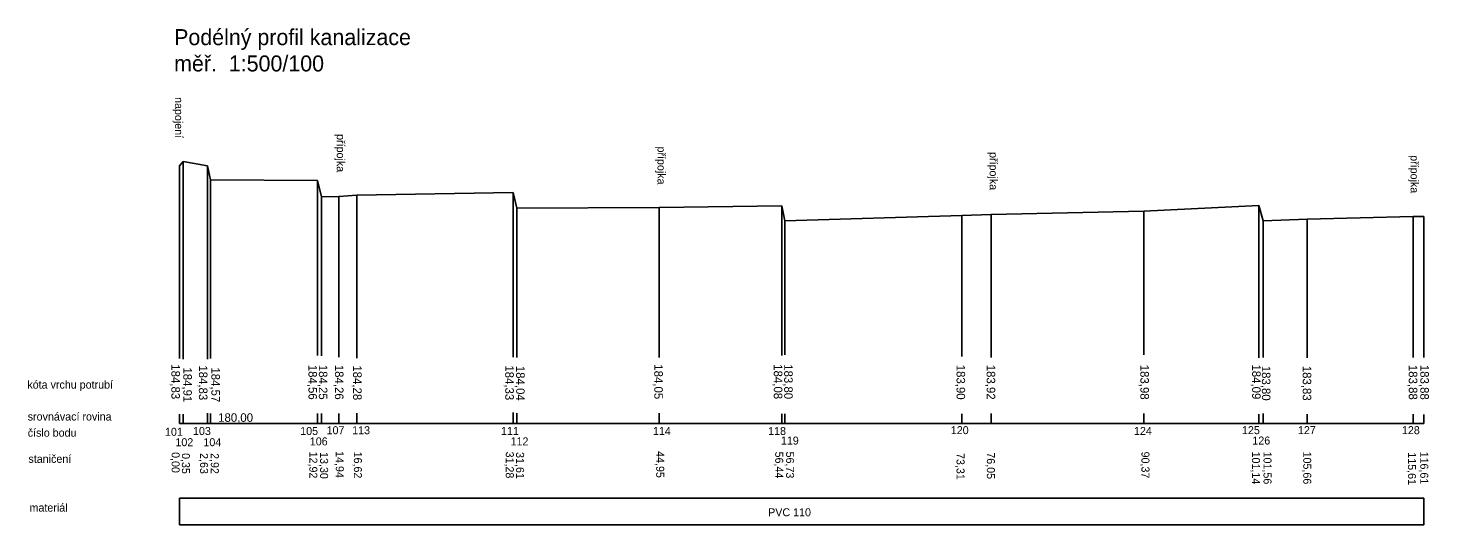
# Model space of a CAD drawing. Extents: x -598400 to -598043, y -1172615 to -1172551.
# Drawn here: x -598174.5 to -598043.2, y -1172597.3 to -1172550.7 of the extents above; entities that cross this region are included whole.
import ezdxf

# ---------------------------------------------------------------- set-up
doc = ezdxf.new("R2010")
doc.units = 0
doc.layers.add('2', color=7, linetype='Continuous')

msp = doc.modelspace()

# ---------------------------------------------------------------- linework, layer by layer
at = {"layer": '2'}
for p, q in [((-598159.922, -1172563.234), (-598160.272, -1172563.634)), ((-598160.272, -1172581.688), (-598160.272, -1172563.634)), ((-598157.642, -1172563.634), (-598159.922, -1172563.234)), ((-598159.922, -1172581.737), (-598159.922, -1172563.234)), ((-598157.352, -1172564.934), (-598157.642, -1172563.634)), ((-598157.642, -1172581.737), (-598157.642, -1172563.634)), ((-598147.352, -1172564.984), (-598157.352, -1172564.934)), ((-598157.352, -1172581.688), (-598157.352, -1172564.934)), ((-598146.972, -1172566.534), (-598147.352, -1172564.984)), ((-598147.352, -1172581.397), (-598147.352, -1172564.984)), ((-598145.332, -1172566.484), (-598146.972, -1172566.534)), ((-598143.652, -1172566.384), (-598145.332, -1172566.484)), ((-598145.332, -1172581.543), (-598145.332, -1172566.484)), ((-598128.992, -1172566.134), (-598143.652, -1172566.384)), ((-598143.652, -1172581.64), (-598143.652, -1172566.384)), ((-598128.662, -1172567.584), (-598128.992, -1172566.134)), ((-598128.992, -1172581.543), (-598128.992, -1172566.134)), ((-598146.972, -1172581.445), (-598146.972, -1172566.534)), ((-598115.322, -1172567.534), (-598128.662, -1172567.584)), ((-598128.662, -1172581.591), (-598128.662, -1172567.584)), ((-598103.832, -1172567.384), (-598115.322, -1172567.534)), ((-598115.322, -1172581.591), (-598115.322, -1172567.534)), ((-598103.542, -1172568.784), (-598103.832, -1172567.384)), ((-598103.832, -1172581.39), (-598103.832, -1172567.384)), ((-598059.132, -1172567.334), (-598069.902, -1172567.884)), ((-598058.712, -1172568.784), (-598059.132, -1172567.334)), ((-598059.132, -1172581.614), (-598059.132, -1172567.334)), ((-598086.962, -1172568.284), (-598103.542, -1172568.784)), ((-598103.542, -1172581.341), (-598103.542, -1172568.784)), ((-598084.222, -1172568.184), (-598086.962, -1172568.284)), ((-598086.962, -1172581.487), (-598086.962, -1172568.284)), ((-598069.902, -1172567.884), (-598084.222, -1172568.184)), ((-598084.222, -1172581.584), (-598084.222, -1172568.184)), ((-598069.902, -1172581.341), (-598069.902, -1172567.884)), ((-598054.612, -1172568.634), (-598058.712, -1172568.784)), ((-598058.712, -1172568.784), (-598058.712, -1172572.884)), ((-598058.712, -1172581.572), (-598058.712, -1172568.784)), ((-598044.662, -1172568.384), (-598054.612, -1172568.634)), ((-598054.612, -1172581.614), (-598054.612, -1172568.634)), ((-598043.662, -1172568.384), (-598044.662, -1172568.384)), ((-598044.662, -1172581.572), (-598044.662, -1172568.384)), ((-598043.662, -1172581.572), (-598043.662, -1172568.384)), ((-598160.272, -1172587.784), (-598160.272, -1172586.887)), ((-598159.922, -1172587.784), (-598159.922, -1172586.887)), ((-598157.642, -1172587.784), (-598157.642, -1172586.789)), ((-598157.352, -1172587.784), (-598157.352, -1172586.838)), ((-598147.352, -1172587.784), (-598147.352, -1172586.838)), ((-598146.972, -1172587.784), (-598146.972, -1172586.838)), ((-598145.332, -1172587.784), (-598145.332, -1172586.838)), ((-598143.652, -1172587.784), (-598143.652, -1172586.789)), ((-598128.992, -1172587.784), (-598128.992, -1172586.741)), ((-598128.662, -1172587.784), (-598128.662, -1172586.789)), ((-598115.322, -1172587.784), (-598115.322, -1172586.789)), ((-598103.832, -1172587.784), (-598103.832, -1172586.882)), ((-598103.542, -1172587.784), (-598103.542, -1172586.882)), ((-598086.962, -1172587.784), (-598086.962, -1172586.882)), ((-598084.222, -1172587.784), (-598084.222, -1172586.833)), ((-598069.902, -1172587.784), (-598069.902, -1172586.833)), ((-598059.132, -1172587.784), (-598059.132, -1172586.887)), ((-598058.712, -1172587.784), (-598058.712, -1172586.845)), ((-598054.612, -1172587.784), (-598054.612, -1172586.887)), ((-598044.662, -1172587.784), (-598044.662, -1172586.887)), ((-598043.662, -1172587.784), (-598043.662, -1172586.928)), ((-598160.272, -1172587.784), (-598159.922, -1172587.784)), ((-598159.922, -1172587.784), (-598157.642, -1172587.784)), ((-598157.642, -1172587.784), (-598157.352, -1172587.784)), ((-598157.352, -1172587.784), (-598147.352, -1172587.784)), ((-598147.352, -1172587.784), (-598146.972, -1172587.784)), ((-598146.972, -1172587.784), (-598145.332, -1172587.784)), ((-598145.332, -1172587.784), (-598143.652, -1172587.784)), ((-598143.652, -1172587.784), (-598128.992, -1172587.784)), ((-598128.992, -1172587.784), (-598128.662, -1172587.784)), ((-598128.662, -1172587.784), (-598115.322, -1172587.784)), ((-598115.322, -1172587.784), (-598103.832, -1172587.784)), ((-598103.832, -1172587.784), (-598103.542, -1172587.784)), ((-598103.542, -1172587.784), (-598086.962, -1172587.784)), ((-598086.962, -1172587.784), (-598084.222, -1172587.784)), ((-598084.222, -1172587.784), (-598069.902, -1172587.784)), ((-598069.902, -1172587.784), (-598059.132, -1172587.784)), ((-598059.132, -1172587.784), (-598058.712, -1172587.784)), ((-598058.712, -1172587.784), (-598054.612, -1172587.784)), ((-598054.612, -1172587.784), (-598044.662, -1172587.784)), ((-598044.662, -1172587.784), (-598043.662, -1172587.784)), ((-598160.272, -1172594.784), (-598159.922, -1172594.784)), ((-598160.272, -1172597.284), (-598160.272, -1172594.784)), ((-598159.922, -1172594.784), (-598157.642, -1172594.784)), ((-598157.642, -1172594.784), (-598157.352, -1172594.784)), ((-598157.352, -1172594.784), (-598147.352, -1172594.784)), ((-598147.352, -1172594.784), (-598146.972, -1172594.784)), ((-598146.972, -1172594.784), (-598145.332, -1172594.784)), ((-598145.332, -1172594.784), (-598143.652, -1172594.784)), ((-598143.652, -1172594.784), (-598128.992, -1172594.784)), ((-598128.992, -1172594.784), (-598128.662, -1172594.784)), ((-598128.662, -1172594.784), (-598115.322, -1172594.784)), ((-598115.322, -1172594.784), (-598103.832, -1172594.784)), ((-598103.832, -1172594.784), (-598103.542, -1172594.784)), ((-598103.542, -1172594.784), (-598086.962, -1172594.784)), ((-598086.962, -1172594.784), (-598084.222, -1172594.784)), ((-598084.222, -1172594.784), (-598069.902, -1172594.784)), ((-598069.902, -1172594.784), (-598059.132, -1172594.784)), ((-598059.132, -1172594.784), (-598058.712, -1172594.784)), ((-598058.712, -1172594.784), (-598054.612, -1172594.784)), ((-598054.612, -1172594.784), (-598044.662, -1172594.784)), ((-598044.662, -1172594.784), (-598043.662, -1172594.784)), ((-598043.662, -1172597.284), (-598043.662, -1172594.784)), ((-598160.272, -1172597.284), (-598159.922, -1172597.284)), ((-598159.922, -1172597.284), (-598157.642, -1172597.284)), ((-598157.642, -1172597.284), (-598157.352, -1172597.284)), ((-598157.352, -1172597.284), (-598147.352, -1172597.284)), ((-598147.352, -1172597.284), (-598146.972, -1172597.284)), ((-598146.972, -1172597.284), (-598145.332, -1172597.284)), ((-598145.332, -1172597.284), (-598143.652, -1172597.284)), ((-598143.652, -1172597.284), (-598128.992, -1172597.284)), ((-598128.992, -1172597.284), (-598128.662, -1172597.284)), ((-598128.662, -1172597.284), (-598115.322, -1172597.284)), ((-598115.322, -1172597.284), (-598103.832, -1172597.284)), ((-598103.832, -1172597.284), (-598103.542, -1172597.284)), ((-598103.542, -1172597.284), (-598086.962, -1172597.284)), ((-598086.962, -1172597.284), (-598084.222, -1172597.284)), ((-598084.222, -1172597.284), (-598069.902, -1172597.284)), ((-598069.902, -1172597.284), (-598059.132, -1172597.284)), ((-598059.132, -1172597.284), (-598058.712, -1172597.284)), ((-598058.712, -1172597.284), (-598054.612, -1172597.284)), ((-598054.612, -1172597.284), (-598044.662, -1172597.284)), ((-598044.662, -1172597.284), (-598043.662, -1172597.284))]:
    msp.add_line(p, q, dxfattribs=at)

# ---------------------------------------------------------------- texts
for s, height, p in [('Podélný profil kanalizace', 1.5, (-598160.774, -1172552.314)), ('měř.  1:500/100', 1.5, (-598160.774, -1172554.779)), ('kóta vrchu potrubí', 0.75, (-598174.525, -1172584.503)), ('srovnávací rovina', 0.75, (-598174.491, -1172587.495)), ('180,00', 0.8, (-598156.65, -1172587.615)), ('číslo bodu', 0.75, (-598174.491, -1172589.008)), ('101', 0.75, (-598161.627, -1172588.926)), ('103', 0.75, (-598159.003, -1172588.851)), ('105', 0.75, (-598148.96, -1172588.851)), ('107', 0.75, (-598146.486, -1172588.777)), ('113', 0.75, (-598144.088, -1172588.777)), ('111', 0.75, (-598130.146, -1172588.851)), ('114', 0.75, (-598115.905, -1172588.851)), ('118', 0.75, (-598105.112, -1172588.851)), ('120', 0.75, (-598087.995, -1172588.772)), ('124', 0.75, (-598070.831, -1172588.847)), ('125', 0.75, (-598060.712, -1172588.772)), ('127', 0.75, (-598055.465, -1172588.772)), ('128', 0.75, (-598045.722, -1172588.772)), ('102', 0.75, (-598160.652, -1172589.899)), ('104', 0.75, (-598158.029, -1172589.899)), ('106', 0.75, (-598148.06, -1172589.824)), ('112', 0.75, (-598129.247, -1172589.824)), ('119', 0.75, (-598103.913, -1172589.75)), ('126', 0.75, (-598059.738, -1172589.745)), ('staničení', 0.75, (-598174.424, -1172591.462)), ('materiál', 0.75, (-598174.323, -1172596.033)), ('PVC 110', 0.75, (-598105.111, -1172596.469))]:
    msp.add_text(s, height=height, dxfattribs=at).set_placement(p)
for s, height, p in [('napojení', 0.75, (-598160.694, -1172557.183)), ('přípojka', 0.75, (-598145.53, -1172560.651)), ('přípojka', 0.75, (-598115.478, -1172561.813)), ('přípojka', 0.75, (-598084.359, -1172562.335)), ('přípojka', 0.75, (-598044.911, -1172562.624)), ('184,83', 0.8, (-598161.029, -1172582.223)), ('184,91', 0.8, (-598159.91, -1172582.514)), ('184,83', 0.8, (-598158.45, -1172582.32)), ('184,57', 0.8, (-598157.283, -1172582.514)), ('184,56', 0.8, (-598148.184, -1172582.271)), ('184,25', 0.8, (-598147.211, -1172582.271)), ('184,26', 0.8, (-598145.703, -1172582.271)), ('184,28', 0.8, (-598144, -1172582.32)), ('184,33', 0.8, (-598129.744, -1172582.32)), ('184,04', 0.8, (-598128.722, -1172582.368)), ('184,05', 0.8, (-598115.78, -1172582.223)), ('184,08', 0.8, (-598104.581, -1172582.216)), ('183,80', 0.8, (-598103.608, -1172582.216)), ('183,90', 0.8, (-598087.455, -1172582.265)), ('183,92', 0.8, (-598084.633, -1172582.265)), ('183,98', 0.8, (-598070.231, -1172582.265)), ('184,09', 0.8, (-598059.758, -1172582.236)), ('183,80', 0.8, (-598058.844, -1172582.361)), ('183,83', 0.8, (-598055.018, -1172582.361)), ('183,88', 0.8, (-598045.08, -1172582.278)), ('183,88', 0.8, (-598043.999, -1172582.278)), ('0,00', 0.75, (-598161.006, -1172590.453)), ('0,35', 0.75, (-598160.042, -1172590.545)), ('2,63', 0.75, (-598158.343, -1172590.545)), ('2,92', 0.75, (-598157.333, -1172590.545)), ('12,92', 0.75, (-598148.104, -1172590.407)), ('13,30', 0.75, (-598147.094, -1172590.453)), ('14,94', 0.75, (-598145.625, -1172590.361)), ('16,62', 0.75, (-598143.926, -1172590.407)), ('31,28', 0.75, (-598129.693, -1172590.407)), ('31,61', 0.75, (-598128.729, -1172590.453)), ('44,95', 0.75, (-598115.598, -1172590.361)), ('56,44', 0.75, (-598104.447, -1172590.405)), ('56,73', 0.75, (-598103.431, -1172590.405)), ('73,31', 0.75, (-598087.457, -1172590.54)), ('76,05', 0.75, (-598084.615, -1172590.472)), ('90,37', 0.75, (-598070.13, -1172590.405)), ('101,14', 0.75, (-598059.774, -1172590.405)), ('101,56', 0.75, (-598058.691, -1172590.405)), ('105,66', 0.75, (-598054.968, -1172590.405)), ('115,61', 0.75, (-598045.154, -1172590.472)), ('116,61', 0.75, (-598044.003, -1172590.405))]:
    msp.add_text(s, height=height, rotation=270, dxfattribs=at).set_placement(p)

doc.saveas('drawing.dxf')
